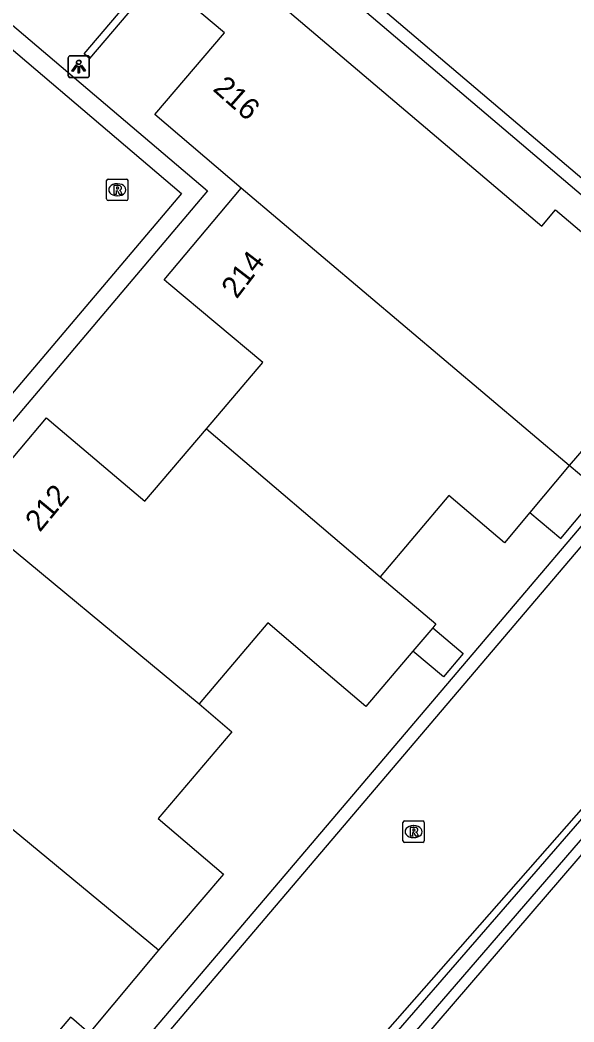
# Model space of a CAD drawing. Extents: x 156414 to 157775, y 382335 to 383765.
# Drawn here: x 157120.56 to 157146.41, y 382648.39 to 382695.11 of the extents above; entities that cross this region are included whole.
import ezdxf

# ---------------------------------------------------------------- set-up
doc = ezdxf.new("R2010")
doc.units = 0
for name, color, linetype in [('IMGEO_Greppel_droge_sloot', 7, 'Continuous'), ('IMGEO_Groenvoorziening', 7, 'Continuous'), ('IMGEO_Haag', 7, 'Continuous'), ('IMGEO_Lichtpunt', 7, 'Continuous'), ('IMGEO_Pand', 7, 'Continuous'), ('IMGEO_Pand_nummerreeks', 7, 'Continuous'), ('IMGEO_Rijbaan_lokaal_open', 7, 'Continuous'), ('IMGEO_Rioolput', 7, 'Continuous'), ('IMGEO_Voetpad_open', 7, 'Continuous')]:
    doc.layers.add(name, color=color, linetype=linetype)

msp = doc.modelspace()

# ---------------------------------------------------------------- linework, layer by layer
at = {"layer": 'IMGEO_Greppel_droge_sloot'}
for points in [[(157158.363, 382671.096), (157147.522, 382657.801), (157147.284, 382657.525), (157104.993, 382608.584)], [(157104.357, 382609.021), (157146.888, 382657.977), (157153.613, 382665.935), (157157.196, 382670.456)]]:
    msp.add_lwpolyline(points, dxfattribs=at)
at = {"layer": 'IMGEO_Groenvoorziening'}
for points in [[(157103.531, 382609.159), (157146.978, 382658.541), (157153.513, 382666.961)], [(157148.023, 382657.655), (157139.342, 382647.567), (157122.211, 382626.599)]]:
    msp.add_lwpolyline(points, dxfattribs=at)
at = {"layer": 'IMGEO_Haag'}
for points in [[(157083.499, 382631.489), (157100.998, 382616.771), (157155.234, 382680.544), (157057.039, 382763.88), (157024.771, 382733.376), (156998.927, 382703.165), (157017.374, 382687.547)], [(157083.884, 382631.949), (157100.928, 382617.614), (157154.388, 382680.475), (157057.061, 382763.075), (157025.206, 382732.962), (157021.009, 382728.308), (156999.775, 382703.233), (157017.757, 382688.01)]]:
    msp.add_lwpolyline(points, dxfattribs=at)
at = {"layer": 'IMGEO_Lichtpunt'}
for p, q in [((157122.792, 382693.331), (157122.792, 382692.524)), ((157122.792, 382693.331), (157122.792, 382692.524)), ((157122.808, 382693.35), (157122.808, 382692.543)), ((157122.808, 382693.35), (157122.808, 382692.543)), ((157123.694, 382693.426), (157122.886, 382693.426)), ((157123.694, 382693.426), (157122.886, 382693.426)), ((157123.71, 382693.445), (157122.902, 382693.445)), ((157123.71, 382693.445), (157122.902, 382693.445)), ((157123.788, 382692.524), (157123.788, 382693.331)), ((157123.788, 382692.524), (157123.788, 382693.331)), ((157123.804, 382692.543), (157123.804, 382693.35)), ((157123.804, 382692.543), (157123.804, 382693.35)), ((157122.886, 382692.43), (157123.694, 382692.43)), ((157122.886, 382692.43), (157123.694, 382692.43)), ((157122.902, 382692.449), (157123.71, 382692.449)), ((157122.902, 382692.449), (157123.71, 382692.449))]:
    msp.add_line(p, q, dxfattribs=at)
for points in [[(157123.166, 382692.995), (157123.205, 382692.967), (157123.017, 382692.705), (157122.979, 382692.732), (157123.166, 382692.995)], [(157123.182, 382693.014), (157123.221, 382692.986), (157123.033, 382692.724), (157122.995, 382692.751), (157123.182, 382693.014)], [(157123.268, 382692.947), (157123.315, 382692.947), (157123.315, 382692.625), (157123.268, 382692.625), (157123.268, 382692.947)], [(157123.284, 382692.966), (157123.331, 382692.966), (157123.331, 382692.644), (157123.284, 382692.644), (157123.284, 382692.966)], [(157123.378, 382692.967), (157123.416, 382692.994), (157123.603, 382692.732), (157123.564, 382692.704), (157123.378, 382692.967)], [(157123.394, 382692.986), (157123.432, 382693.013), (157123.619, 382692.751), (157123.58, 382692.723), (157123.394, 382692.986)]]:
    msp.add_lwpolyline(points, dxfattribs=at)
for centre in [(157123.291, 382693.129), (157123.307, 382693.148)]:
    msp.add_circle(centre, 0.0994, dxfattribs=at)
for centre, start, end in [((157122.886, 382693.331), 90, 180), ((157122.886, 382693.331), 90, 180), ((157122.902, 382693.35), 90, 180), ((157122.902, 382693.35), 90, 180), ((157123.694, 382693.331), 0, 90), ((157123.694, 382693.331), 0, 90), ((157123.71, 382693.35), 0, 90), ((157123.71, 382693.35), 0, 90), ((157122.886, 382692.524), 180, 270), ((157122.886, 382692.524), 180, 270), ((157122.902, 382692.543), 180, 270), ((157122.902, 382692.543), 180, 270), ((157123.694, 382692.524), 270, 0), ((157123.694, 382692.524), 270, 360), ((157123.71, 382692.543), 270, 0), ((157123.71, 382692.543), 270, 360)]:
    msp.add_arc(centre, 0.0946, start, end, dxfattribs=at)
at = {"layer": 'IMGEO_Pand'}
for points in [[(157130.881, 382687.273), (157126.852, 382690.703), (157130.093, 382694.51), (157127.012, 382697.102), (157123.796, 382693.324), (157123.549, 382693.537), (157128.53, 382699.388), (157144.908, 382685.505), (157145.549, 382686.261), (157151.84, 382680.92), (157149.275, 382677.933), (157146.187, 382674.338)], [(157129.258, 382676.052), (157131.89, 382679.135), (157127.504, 382682.81), (157127.291, 382682.988), (157130.881, 382687.273)], [(157146.187, 382674.338), (157130.881, 382687.273)], [(157118.089, 382672.174), (157121.796, 382676.554), (157122.029, 382676.356), (157126.376, 382672.678), (157129.258, 382676.052)], [(157129.258, 382676.052), (157137.37, 382669.137)], [(157146.187, 382674.338), (157144.349, 382672.147)], [(157144.349, 382672.147), (157145.794, 382670.935), (157147.628, 382673.12), (157146.187, 382674.338)], [(157144.349, 382672.147), (157143.164, 382670.735), (157140.572, 382672.935), (157137.37, 382669.137)], [(157118.089, 382672.174), (157128.91, 382663.224)], [(157137.37, 382669.137), (157139.969, 382666.945), (157139.819, 382666.769)], [(157138.894, 382665.684), (157136.691, 382663.101), (157134.835, 382664.683), (157132.126, 382666.994), (157128.91, 382663.224)], [(157139.819, 382666.769), (157141.244, 382665.567), (157140.325, 382664.477), (157138.894, 382665.684)], [(157139.819, 382666.769), (157138.894, 382665.684)], [(157128.91, 382663.224), (157130.443, 382661.918), (157126.999, 382657.875), (157130.056, 382655.276), (157127.017, 382651.732)], [(157127.017, 382651.732), (157116.225, 382660.644)], [(157127.017, 382651.732), (157123.783, 382647.87), (157122.956, 382648.571), (157122.913, 382648.607), (157119.582, 382644.69)]]:
    msp.add_lwpolyline(points, dxfattribs=at)
at = {"layer": 'IMGEO_Rijbaan_lokaal_open'}
msp.add_lwpolyline([(157082.895, 382652.477), (157080.769, 382654.32), (157116.675, 382696.742), (157128.088, 382687.021), (157092.121, 382644.588), (157089.934, 382646.493)], dxfattribs=at)
at = {"layer": 'IMGEO_Rioolput'}
for p, q in [((157124.595, 382686.768), (157124.595, 382687.62)), ((157124.67, 382687.694), (157125.522, 382687.694)), ((157125.596, 382687.62), (157125.596, 382686.768)), ((157125.083, 382687.474), (157125.108, 382687.474)), ((157125.522, 382686.694), (157124.67, 382686.694)), ((157125.106, 382686.914), (157125.081, 382686.914)), ((157138.423, 382656.834), (157138.423, 382657.686)), ((157138.498, 382657.76), (157139.35, 382657.76)), ((157139.424, 382657.686), (157139.424, 382656.834)), ((157138.911, 382657.54), (157138.936, 382657.54)), ((157139.35, 382656.76), (157138.498, 382656.76)), ((157138.934, 382656.98), (157138.909, 382656.98))]:
    msp.add_line(p, q, dxfattribs=at)
for points in [[(157124.595, 382686.768), (157124.595, 382687.62)], [(157124.67, 382687.694), (157125.522, 382687.694)], [(157125.596, 382687.62), (157125.596, 382686.768)], [(157125.184, 382687.392), (157124.932, 382687.394), (157124.932, 382686.994)], [(157124.932, 382686.994), (157125.056, 382686.994), (157125.056, 382687.156), (157125.067, 382687.156)], [(157125.11, 382687.313), (157125.056, 382687.313), (157125.056, 382687.232)], [(157125.056, 382687.232), (157125.108, 382687.232)], [(157125.114, 382687.127), (157125.185, 382686.994), (157125.325, 382686.994), (157125.26, 382687.12)], [(157125.522, 382686.694), (157124.67, 382686.694)], [(157138.423, 382656.834), (157138.423, 382657.686)], [(157138.498, 382657.76), (157139.35, 382657.76)], [(157139.424, 382657.686), (157139.424, 382656.834)], [(157139.012, 382657.458), (157138.76, 382657.46), (157138.76, 382657.06)], [(157138.76, 382657.06), (157138.884, 382657.06), (157138.884, 382657.222), (157138.895, 382657.222)], [(157138.938, 382657.379), (157138.884, 382657.379), (157138.884, 382657.298)], [(157138.884, 382657.298), (157138.936, 382657.298)], [(157138.942, 382657.193), (157139.013, 382657.06), (157139.153, 382657.06), (157139.088, 382657.186)], [(157139.35, 382656.76), (157138.498, 382656.76)]]:
    msp.add_lwpolyline(points, dxfattribs=at)
for centre, radius, start, end in [((157124.672, 382687.618), 0.0765, 91.552, 178.448), ((157124.672, 382687.618), 0.0765, 91.552, 178.448), ((157125.52, 382687.618), 0.0765, 1.552, 88.448), ((157125.52, 382687.618), 0.0765, 1.552, 88.448), ((157125.066, 382687.103), 0.0533, 26.0293, 88.6989), ((157125.092, 382687.421), 0.19, 274.7715, 282.9687), ((157125.116, 382687.217), 0.0964, 77.0061, 93.1865), ((157125.13, 382687.274), 0.0378, 276.6634, 79.6772), ((157125.183, 382687.282), 0.109, 350.3612, 89.416), ((157125.181, 382687.282), 0.112, 277.5842, 350.9817), ((157125.165, 382687.067), 0.108, 29.5134, 73.7905), ((157124.672, 382686.77), 0.0765, 181.552, 268.448), ((157124.672, 382686.77), 0.0765, 181.552, 268.448), ((157125.52, 382686.77), 0.0765, 271.552, 358.448), ((157125.52, 382686.77), 0.0765, 271.552, 358.448), ((157138.5, 382657.684), 0.0765, 91.552, 178.448), ((157138.5, 382657.684), 0.0765, 91.552, 178.448), ((157139.348, 382657.684), 0.0765, 1.552, 88.448), ((157139.348, 382657.684), 0.0765, 1.552, 88.448), ((157138.894, 382657.169), 0.0533, 26.0293, 88.6989), ((157138.92, 382657.487), 0.19, 274.7715, 282.9687), ((157138.944, 382657.283), 0.0964, 77.0061, 93.1865), ((157138.958, 382657.34), 0.0378, 276.6634, 79.6772), ((157139.011, 382657.348), 0.109, 350.3612, 89.416), ((157139.009, 382657.348), 0.112, 277.5842, 350.9817), ((157138.993, 382657.133), 0.108, 29.5134, 73.7905), ((157138.5, 382656.836), 0.0765, 181.552, 268.448), ((157138.5, 382656.836), 0.0765, 181.552, 268.448), ((157139.348, 382656.836), 0.0765, 271.552, 358.448), ((157139.348, 382656.836), 0.0765, 271.552, 358.448)]:
    msp.add_arc(centre, radius, start, end, dxfattribs=at)
for centre, major_axis, ratio, start_param, end_param in [((157125.082, 382687.194), (-0.387, 0.002), 0.722429, 4.712389, 7.853982), ((157125.107, 382687.194), (-0.39, 0.002), 0.717154, 1.570796, 4.712389), ((157138.91, 382657.26), (-0.387, 0.002), 0.722429, 4.712389, 7.853982), ((157138.935, 382657.26), (-0.39, 0.002), 0.717154, 1.570796, 4.712389)]:
    msp.add_ellipse(centre, major_axis=major_axis, ratio=ratio, start_param=start_param, end_param=end_param, dxfattribs=at)
at = {"layer": 'IMGEO_Voetpad_open'}
msp.add_lwpolyline([(157082.363, 382651.78), (157079.465, 382654.239), (157116.559, 382697.961), (157129.305, 382687.146), (157092.239, 382643.346), (157089.335, 382645.82)], dxfattribs=at)

# ---------------------------------------------------------------- texts
at = {"layer": 'IMGEO_Pand_nummerreeks'}
for s, rotation, p in [('216', 318.5121, (157129.514, 382691.848)), ('214', 52.5059, (157130.666, 382682.071)), ('212', 50.4489, (157121.481, 382671.193))]:
    msp.add_text(s, height=1, rotation=rotation, dxfattribs=at).set_placement(p)

doc.saveas('drawing.dxf')
